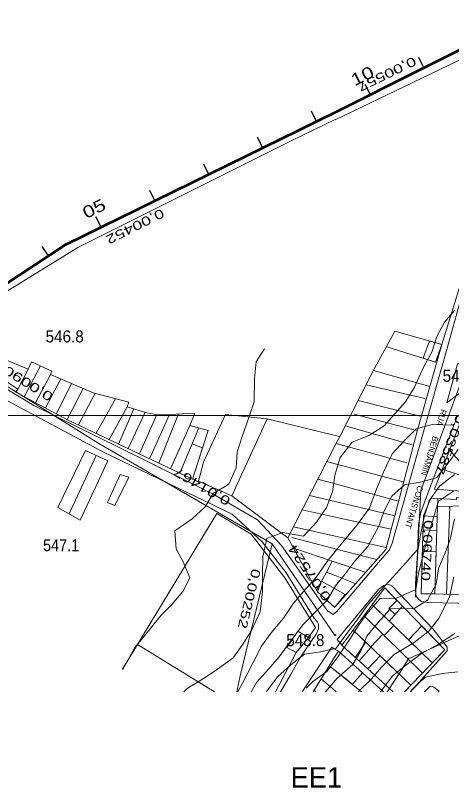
# Model space of a CAD drawing. Extents: x 949 to 2631, y -1701 to -513.
# Drawn here: x 1121.5 to 1266.8, y -944.6 to -687.3 of the extents above; entities that cross this region are included whole.
import ezdxf
from ezdxf.enums import TextEntityAlignment as Align

# ---------------------------------------------------------------- set-up
doc = ezdxf.new("R2010")
doc.units = 0
doc.header["$LTSCALE"] = 1.2
for name, color, linetype, lineweight in [('10', 7, 'Continuous', 13), ('11', 7, 'Continuous', 13), ('16', 7, 'Continuous', 13), ('17', 7, 'Continuous', 13), ('20', 7, 'Continuous', 13), ('21', 7, 'Continuous', 13), ('28', 7, 'Continuous', 13), ('29', 7, 'Continuous', 25), ('3', 7, 'Continuous', 13), ('32', 7, 'Continuous', 13), ('34', 7, 'Continuous', 35), ('4', 7, 'Continuous', 13), ('5', 7, 'Continuous', 13), ('7', 7, 'Continuous', 35), ('8', 7, 'Continuous', 13), ('9', 7, 'Continuous', 13)]:
    doc.layers.add(name, color=color, linetype=linetype, lineweight=lineweight)
doc.layers.add('30', color=7, linetype='Continuous')
doc.layers.add('63', color=7, linetype='Continuous')

msp = doc.modelspace()

# ---------------------------------------------------------------- linework, layer by layer
at = {"layer": '10'}
for p, q in [((1245.192, -797.752), (1261.442, -802.862)), ((1240.782, -805.622), (1259.532, -810.932)), ((1257.822, -814.992), (1238.302, -810.442)), ((1235.652, -815.622), (1256.272, -820.902)), ((1255.072, -825.582), (1234.282, -820.212)), ((1253.662, -830.392), (1231.342, -824.022)), ((1229.492, -827.632), (1228.032, -827.282)), ((1251.832, -836.412), (1228.292, -829.992)), ((1250.662, -842.732), (1228.032, -836.702)), ((1274.812, -842.222), (1263.632, -838.542)), ((1249.082, -849.142), (1228.032, -843.402)), ((1262.232, -848.322), (1262.132, -850.962)), ((1247.902, -854.062), (1228.032, -849.302)), ((1265.102, -880.172), (1266.162, -850.882)), ((1262.022, -854.372), (1257.372, -854.062)), ((1246.592, -858.532), (1228.032, -854.502)), ((1257.242, -858.732), (1261.882, -858.912)), ((1245.012, -864.662), (1228.032, -860.842)), ((1241.782, -868.582), (1228.032, -865.052)), ((1237.972, -872.882), (1228.032, -869.542)), ((1234.612, -876.622), (1228.032, -873.992)), ((1231.302, -880.252), (1228.032, -878.432)), ((1227.862, -884.582), (1228.032, -884.362)), ((1260.342, -903.062), (1240.342, -883.662)), ((1246.022, -889.172), (1250.432, -884.152)), ((1237.572, -887.332), (1257.062, -906.472)), ((1253.212, -910.472), (1233.952, -892.122)), ((1247.532, -890.632), (1244.322, -893.962)), ((1239.842, -897.742), (1243.912, -893.562)), ((1239.972, -897.862), (1235.982, -902.412)), ((1228.032, -900.872), (1229.092, -899.192)), ((1229.092, -899.192), (1244.127, -912.671)), ((1236.807, -912.671), (1228.032, -905.662)), ((1228.032, -912.422), (1228.325, -912.671))]:
    msp.add_line(p, q, dxfattribs=at)
for points in [[(1263.552, -796.972), (1270.582, -773.952), (1277.212, -755.552), (1281.162, -742.942), (1283.902, -733.522), (1284.832, -723.762), (1283.832, -713.442), (1279.292, -699.272), (1283.622, -698.382), (1279.872, -687.332)], [(1228.032, -884.382), (1244.852, -865.302), (1255.252, -825.842), (1263.552, -796.972), (1247.852, -792.572), (1240.572, -806.012)], [(1240.572, -806.012), (1229.492, -827.632), (1228.032, -830.482)], [(1266.112, -832.082), (1274.812, -842.222), (1276.482, -841.402)], [(1272.622, -850.772), (1262.132, -850.962), (1261.222, -880.112)], [(1228.032, -878.432), (1223.432, -875.862), (1222.052, -879.402), (1227.862, -884.582)], [(1251.095, -912.671), (1264.532, -898.712), (1244.552, -878.082), (1230.162, -897.132), (1247.31, -912.671)], [(1228.032, -905.662), (1226.032, -904.062), (1228.032, -900.872)]]:
    msp.add_lwpolyline(points, dxfattribs=at)
for points in [[(1261.072, -845.232), (1267.812, -827.642), (1269.922, -822.102), (1274.252, -818.022), (1279.762, -814.312), (1292.232, -808.992), (1320.002, -800.432), (1348.632, -792.352), (1351.992, -804.332), (1353.582, -825.712), (1335.712, -830.512), (1320.662, -833.722), (1320.662, -842.402), (1303.592, -845.722), (1302.402, -842.752), (1293.012, -844.962), (1278.902, -846.532)], [(1256.682, -880.042), (1352.952, -881.502), (1354.362, -854.642), (1353.462, -827.572), (1344.032, -830.402), (1344.542, -832.862), (1322.142, -835.402), (1323.442, -842.082), (1332.992, -839.992), (1333.122, -848.522), (1321.962, -849.102), (1321.992, -846.352), (1317.392, -846.522), (1317.392, -846.502), (1317.352, -850.052), (1289.782, -850.232), (1276.142, -850.612), (1272.622, -850.772), (1272.632, -848.042), (1268.442, -847.922), (1268.432, -848.582), (1259.812, -848.222), (1257.372, -854.062), (1257.092, -864.242)], [(1180.422, -841.832), (1176.262, -839.852), (1180.352, -830.062), (1183.772, -831.462)], [(1152.142, -849.642), (1156.392, -840.252), (1159.212, -841.172), (1154.532, -850.642)], [(1214.942, -899.642), (1219.112, -894.582), (1215.512, -892.552), (1211.922, -897.992)]]:
    msp.add_lwpolyline(points, close=True, dxfattribs=at)
at = {"layer": '11'}
msp.add_line((1233.722, -910.202), (1228.032, -905.662), dxfattribs=at)
for points in [[(1261.442, -802.862), (1263.552, -796.972), (1259.402, -795.792), (1257.302, -801.562)], [(1261.222, -880.112), (1261.662, -866.012), (1257.052, -865.982), (1256.682, -880.042)], [(1246.022, -889.172), (1240.342, -883.662), (1244.552, -878.082), (1248.582, -882.242), (1245.912, -885.002), (1247.952, -886.982)], [(1230.162, -897.132), (1233.952, -892.122), (1238.212, -896.182), (1234.692, -901.242)], [(1260.342, -903.062), (1264.532, -898.712), (1256.832, -890.762), (1252.402, -895.362)]]:
    msp.add_lwpolyline(points, close=True, dxfattribs=at)
for points in [[(1228.032, -884.362), (1231.302, -880.252), (1228.032, -878.432)], [(1228.032, -900.872), (1229.092, -899.192), (1237.142, -906.412), (1233.722, -910.202)], [(1247.309, -912.671), (1238.852, -905.012), (1242.972, -900.722), (1253.212, -910.472), (1251.095, -912.671)]]:
    msp.add_lwpolyline(points, dxfattribs=at)
at = {"layer": '16'}
for points in [[(1202.112, -855.382), (1187.532, -846.942), (1163.202, -834.882), (1127.632, -817.342), (1118.622, -811.832), (1109.572, -805.222), (1096.832, -794.962), (1090.042, -790.322)], [(1203.712, -862.782), (1193.662, -853.522), (1150.832, -832.832), (1117.142, -814.832), (1102.062, -803.452), (1089.692, -794.062), (1088.382, -793.152)], [(1224.712, -884.792), (1210.102, -863.922), (1202.112, -855.382)], [(1220.972, -888.142), (1211.632, -873.082), (1203.712, -862.782)]]:
    msp.add_lwpolyline(points, dxfattribs=at)
at = {"layer": '17'}
msp.add_line((1228.032, -820.632), (1041.978, -820.632), dxfattribs=at)
at = {"layer": '20'}
msp.add_lwpolyline([(1265.162, -798.592), (1271.482, -775.802), (1278.842, -753.712), (1284.172, -736.542), (1286.492, -726.102), (1287.232, -717.382), (1287.112, -707.762), (1284.202, -694.352), (1281.522, -687.302)], dxfattribs=at)
at = {"layer": '21'}
msp.add_line((1438.974, -820.632), (1228.032, -820.632), dxfattribs=at)
at = {"layer": '28'}
msp.add_line((1227.934, -894.089), (1206.944, -863.359), dxfattribs=at)
for points in [[(1228.032, -722.015), (1213.354, -729.079), (1142.284, -764.629), (1093.004, -794.959)], [(1195.217, -912.671), (1196.314, -907.439), (1206.944, -863.359), (1149.214, -829.919), (1093.004, -794.959), (1083.134, -786.589)]]:
    msp.add_lwpolyline(points, dxfattribs=at)
at = {"layer": '29'}
for p, q in [((1257.579, -704.767), (1255.862, -701.344)), ((1239.704, -713.737), (1237.987, -710.315)), ((1221.801, -722.652), (1220.114, -719.214)), ((1203.846, -731.462), (1202.159, -728.025)), ((1185.891, -740.272), (1184.204, -736.835)), ((1167.936, -749.083), (1166.25, -745.645)), ((1149.981, -757.893), (1148.295, -754.456)), ((1132.455, -767.454), (1130.354, -764.253))]:
    msp.add_line(p, q, dxfattribs=at)
at = {"layer": '29', "lineweight": 53}
msp.add_lwpolyline([(1073.88, -805.132), (1073.202, -806.436), (1075.81, -807.79), (1086.799, -786.637), (1101.557, -787.729), (1138.256, -763.647), (1228.052, -719.585), (1284.057, -691.479), (1304.502, -688.949), (1348.513, -782.198), (1360.795, -834.118)], dxfattribs=at)
at = {"layer": '29'}
msp.add_lwpolyline([(1086.799, -786.637), (1101.557, -787.729), (1138.256, -763.647), (1228.052, -719.585), (1284.057, -691.479), (1304.502, -688.949), (1348.513, -782.198), (1360.795, -834.118), (1364.521, -833.237)], dxfattribs=at)
at = {"layer": '32'}
msp.add_line((1228.291, -893.957), (1228.032, -893.577), dxfattribs=at)
for points in [[(1438.974, -759.256), (1432.401, -736.237), (1361.321, -708.887), (1309.391, -691.567), (1285.701, -694.297), (1228.032, -722.054)], [(1254.721, -881.197), (1256.541, -845.637), (1271.121, -806.437), (1289.341, -728.947), (1285.701, -694.297)]]:
    msp.add_lwpolyline(points, dxfattribs=at)
at = {"layer": '4'}
for points in [[(1267.422, -845.862), (1262.442, -849.192), (1260.582, -855.122), (1258.712, -861.562), (1257.182, -867.412), (1255.742, -873.342), (1254.912, -878.592), (1248.392, -881.522), (1242.982, -881.612), (1238.992, -886.162), (1236.012, -890.312), (1232.892, -895.202), (1228.782, -901.332), (1228.032, -902.302)], [(1272.977, -892.4), (1252.838, -901.45), (1252.633, -901.454), (1252.577, -901.531), (1249.63, -906.151), (1245.258, -912.671)], [(1228.032, -902.302), (1225.182, -905.962), (1220.572, -909.302), (1218.382, -911.412), (1218.372, -911.422)]]:
    msp.add_lwpolyline(points, dxfattribs=at)
at = {"layer": '5'}
for points in [[(1267.822, -785.482), (1264.402, -789.572), (1261.892, -794.342), (1260.202, -799.532), (1257.572, -804.322), (1254.292, -811.382), (1251.302, -816.192), (1247.882, -820.082), (1244.342, -824.052), (1239.152, -827.312), (1233.612, -829.562), (1229.672, -834.672), (1228.032, -840.182)], [(1157.172, -905.232), (1157.182, -905.192), (1161.232, -897.992), (1164.412, -894.042), (1170.062, -887.222), (1173.722, -883.562), (1177.272, -879.262), (1179.522, -874.722), (1177.412, -869.622), (1175.012, -865.102), (1174.522, -859.092), (1180.392, -855.032), (1184.672, -851.122), (1187.382, -846.632), (1192.602, -843.502), (1195.042, -838.072), (1195.282, -832.872), (1196.842, -827.932), (1199.322, -820.942), (1201.042, -816.122), (1201.132, -808.312), (1201.652, -802.772), (1204.482, -798.412)], [(1267.402, -823.812), (1260.302, -823.682), (1254.952, -825.042), (1250.942, -829.102), (1246.942, -833.452), (1244.112, -839.542), (1241.482, -845.742), (1239.452, -851.532), (1235.282, -857.072), (1229.972, -863.542), (1228.032, -865.942)], [(1268.922, -831.942), (1265.482, -836.612), (1261.702, -841.352), (1256.252, -842.822), (1251.082, -843.762), (1246.902, -847.482), (1244.322, -852.382), (1242.542, -857.542), (1238.842, -864.312), (1234.442, -869.342), (1231.122, -873.742), (1228.032, -877.552)], [(1228.032, -840.182), (1227.862, -840.752), (1227.062, -846.032), (1225.112, -851.342), (1221.812, -856.172), (1217.392, -860.822), (1210.532, -859.672), (1205.182, -861.572), (1203.882, -867.732), (1203.812, -873.882), (1203.722, -879.422), (1203.002, -886.072), (1200.122, -892.242), (1197.262, -896.832), (1193.962, -901.412), (1188.812, -905.202), (1184.622, -907.962), (1178.682, -911.622), (1177.53, -912.671)], [(1267.692, -840.292), (1262.782, -844.212), (1259.352, -849.122), (1257.632, -854.522), (1256.402, -860.412), (1255.582, -865.072), (1251.392, -869.822), (1247.432, -874.342), (1243.142, -878.912), (1238.482, -884.162), (1235.552, -888.422), (1231.922, -893.282), (1228.282, -898.182), (1228.032, -898.242)], [(1267.742, -855.022), (1266.312, -861.992), (1264.462, -866.922), (1262.442, -871.592), (1261.662, -876.892), (1258.772, -882.222), (1254.322, -884.972), (1246.432, -885.112), (1242.192, -889.682)], [(1228.032, -865.942), (1225.692, -868.832), (1221.462, -874.802), (1217.372, -879.422), (1214.092, -883.212), (1210.792, -888.152), (1206.652, -893.062), (1203.452, -897.542), (1200.682, -902.972), (1197.162, -909.792), (1195.541, -912.671)], [(1235.644, -912.671), (1240.112, -908.342), (1243.422, -904.522), (1247.612, -900.262), (1254.322, -896.332), (1259.342, -892.362), (1262.402, -888.342), (1266.082, -881.212), (1267.542, -874.362)], [(1228.032, -877.552), (1227.942, -877.662), (1225.282, -882.172), (1221.072, -886.412), (1217.352, -890.322), (1213.772, -894.982), (1209.312, -901.052), (1205.842, -905.022), (1201.732, -909.662), (1200.009, -912.671)], [(1242.192, -889.682), (1238.542, -894.182), (1236.652, -898.852), (1233.912, -903.622), (1228.682, -908.202), (1228.032, -908.952)], [(1267.862, -893.232), (1262.452, -896.892), (1256.802, -899.912), (1250.982, -904.232), (1247.042, -907.372), (1243.902, -911.732), (1243.128, -912.671)], [(1228.032, -898.242), (1223.042, -899.402), (1217.772, -900.212), (1213.232, -903.702), (1208.722, -907.702), (1205.242, -912.512), (1205.146, -912.671)], [(1268.882, -906.102), (1263.692, -906.602), (1257.962, -907.832), (1253.342, -912.272), (1253.08, -912.671)], [(1228.032, -908.952), (1224.852, -912.622), (1224.811, -912.671)]]:
    msp.add_lwpolyline(points, dxfattribs=at)
at = {"layer": '7', "lineweight": 13}
for points in [[(1228.032, -886.382), (1227.342, -886.992), (1225.392, -885.772), (1224.712, -884.792)], [(1220.972, -888.142), (1221.952, -889.332), (1222.382, -890.202), (1222.412, -891.732), (1221.702, -893.562), (1216.172, -901.492), (1212.942, -907.272), (1209.768, -912.671)], [(1228.032, -898.572), (1226.862, -897.892), (1221.952, -905.132), (1216.952, -912.671)]]:
    msp.add_lwpolyline(points, dxfattribs=at)
at = {"layer": '8'}
for p, q in [((1229.092, -899.192), (1228.032, -898.572)), ((1253.064, -912.671), (1265.312, -899.052))]:
    msp.add_line(p, q, dxfattribs=at)
for points in [[(1265.162, -798.592), (1253.822, -838.612), (1247.022, -863.182), (1245.952, -865.542), (1243.032, -868.832), (1228.562, -885.912), (1228.032, -886.382)], [(1268.732, -820.762), (1259.522, -844.752), (1256.512, -852.882), (1255.772, -856.982), (1255.362, -866.522), (1254.802, -876.722), (1254.782, -879.122), (1254.932, -880.832), (1255.742, -881.892), (1256.802, -882.592), (1258.762, -883.002), (1273.872, -883.252)], [(1265.312, -899.052), (1265.252, -897.802), (1260.602, -891.802), (1246.862, -877.352), (1245.692, -876.872), (1244.102, -877.312), (1242.452, -878.602), (1228.632, -895.232), (1230.162, -897.132)], [(1262.676, -912.671), (1262.432, -912.392), (1260.862, -911.202), (1260.102, -910.812), (1259.482, -910.932), (1257.78, -912.671)]]:
    msp.add_lwpolyline(points, dxfattribs=at)
msp.add_lwpolyline([(1265.162, -816.462), (1268.842, -813.642), (1272.472, -810.982), (1274.362, -808.862), (1275.182, -806.422), (1275.922, -802.422), (1268.782, -803.462)], close=True, dxfattribs=at)
at = {"layer": '9'}
for p, q in [((1122.262, -811.802), (1125.712, -805.152)), ((1129.812, -804.112), (1124.402, -814.362)), ((1133.092, -806.952), (1128.162, -816.362)), ((1131.452, -818.122), (1136.552, -808.432)), ((1140.102, -809.952), (1135.102, -820.062)), ((1138.662, -821.962), (1143.972, -811.602)), ((1148.012, -813.222), (1142.502, -823.792)), ((1148.312, -826.552), (1154.792, -815.032)), ((1158.672, -817.792), (1152.672, -828.622)), ((1155.842, -830.142), (1160.932, -818.442)), ((1164.652, -819.522), (1159.002, -831.642)), ((1162.792, -833.442), (1168.532, -820.292)), ((1172.752, -820.282), (1166.102, -835.022)), ((1169.192, -836.492), (1175.772, -820.122)), ((1193.552, -847.372), (1205.342, -821.762)), ((1179.552, -823.952), (1173.142, -838.372)), ((1182.562, -824.782), (1176.262, -839.852)), ((1228.032, -830.482), (1212.202, -861.422)), ((1148.342, -833.932), (1139.312, -853.372)), ((1228.032, -836.702), (1225.232, -835.952)), ((1228.032, -843.402), (1222.232, -841.822)), ((1228.032, -849.302), (1219.462, -847.242)), ((1228.032, -854.502), (1216.972, -852.102)), ((1228.032, -860.842), (1214.102, -857.702)), ((1228.032, -865.052), (1213.502, -861.312)), ((1228.032, -869.542), (1214.082, -864.852)), ((1226.932, -869.172), (1225.132, -872.832)), ((1228.032, -878.432), (1223.432, -875.862)), ((1227.862, -884.582), (1228.032, -884.382)), ((1162.162, -896.952), (1187.783, -912.671)), ((1220.627, -912.671), (1228.032, -900.872)), ((1228.032, -905.662), (1226.032, -904.062)), ((1223.312, -908.392), (1228.032, -912.422)), ((1221.583, -912.671), (1220.942, -912.172))]:
    msp.add_line(p, q, dxfattribs=at)
for points in [[(1107.192, -801.802), (1122.262, -811.802), (1121.632, -812.892), (1138.582, -821.922), (1180.422, -841.832), (1185.662, -825.632), (1179.552, -823.952), (1181.262, -819.812), (1172.912, -820.282), (1168.902, -820.362), (1165.282, -819.702), (1158.672, -817.792), (1159.222, -816.212), (1147.312, -813.042), (1133.092, -806.952), (1133.612, -805.862), (1126.832, -802.742), (1125.712, -805.152), (1109.072, -798.352)], [(1152.282, -835.712), (1143.062, -855.462), (1135.582, -851.312), (1144.792, -832.332)]]:
    msp.add_lwpolyline(points, close=True, dxfattribs=at)
for points in [[(1228.032, -827.282), (1205.342, -821.762), (1191.392, -820.342), (1184.082, -836.182), (1182.422, -842.542), (1193.552, -847.372), (1212.202, -861.422)], [(1157.162, -905.222), (1188.552, -853.312), (1200.012, -860.182), (1211.172, -874.712), (1221.402, -891.242), (1219.112, -894.582), (1214.942, -899.642), (1208.157, -912.671)], [(1212.202, -861.422), (1222.052, -879.402), (1227.862, -884.582)], [(1228.032, -873.992), (1225.132, -872.832), (1221.742, -878.852)]]:
    msp.add_lwpolyline(points, dxfattribs=at)

# ---------------------------------------------------------------- texts
at = {"layer": '10'}
msp.add_text('EE1 ', height=6.772, dxfattribs=at).set_placement((1213.167, -944.628))
at = {"layer": '3'}
for s, width, p in [('546.8', 0.95, (1131.497, -796.28)), ('546.8', 0.95, (1263.785, -809.399)), ('547.1', 0.9, (1130.656, -865.856)), ('548.8', 0.95, (1211.696, -897.498))]:
    msp.add_text(s, height=4, dxfattribs=dict(at, width=width)).set_placement(p)
at = {"layer": '30'}
for s, rotation, width, p in [('0,00452', 206.575, 1.45, (1170.071, -751.58)), ('0,00906', 148.12, 1.5, (1134.326, -813.564)), ('0,01467', 149.918, 1.45, (1193.435, -848.241)), ('0,07524', 124.335, 1.5, (1226.809, -881.251)), ('0,00252', 256.442, 1.4, (1200.288, -871.482))]:
    msp.add_text(s, height=3, rotation=rotation, dxfattribs=dict(at, width=width)).set_placement(p)
at = {"layer": '34'}
for s, rotation, width, p in [('0,00557', 205.702, 1.45, (1254.075, -700.94)), ('0,03587', 249.598, 1.45, (1268.559, -819.897)), ('0,06740', 267.07, 1.4, (1257.634, -855.402))]:
    msp.add_text(s, height=3, rotation=rotation, dxfattribs=dict(at, width=width)).set_placement(p)
at = {"layer": '63', "width": 1.3}
for s, p in [('10', (1237.911, -709.228)), ('05', (1148.528, -753.468))]:
    msp.add_text(s, height=4, rotation=26.014, dxfattribs=at).set_placement(p, align=Align.CENTER)
at = {"layer": '9'}
msp.add_text('RUA     BENJAMIN     CONSTANT', height=2, rotation=253, dxfattribs=at).set_placement((1263.272, -818.372))

doc.saveas('drawing.dxf')
